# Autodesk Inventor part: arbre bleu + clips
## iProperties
Author: Chris...
Created: 2002-01
Part Number: arbre bleu + clips
Material: Par défaut
Document SubType Name: Modélisation
Designer: Chris...
Control State: 0
Master: False
Checked Out: False
PropertySet Name: Design Tracking Control
Shininess: 20.0
PropertySet Name: _Private Model Information
Length Units: 11269
Angle Units: 11283
Time Units: 11279
Mass Units: 11290
Length Display Precision: 3
Angle Display Precision: 2
Compacted: False
Density: 0.0
Volumn: 0.0
Area: 0.0
PropertySet Name: Model Information
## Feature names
1. Balayage1
2. Réseau rectangulaire1 [Rectangular Pattern]
3. Corps dérivé1 [Tagging]
